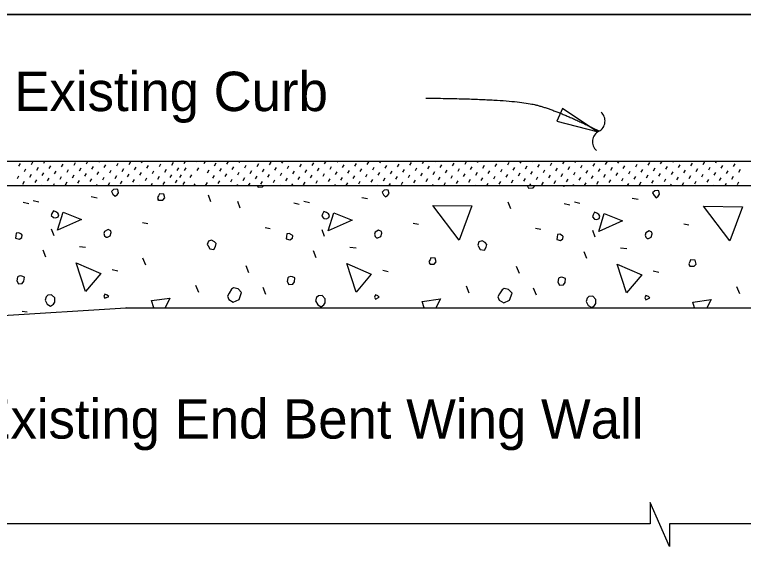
# Model space of a CAD drawing. Extents: x 0 to 41.1, y 0 to 25.9.
# Drawn here: x 12.993 to 16.72, y 6.378 to 9.099 of the extents above; entities that cross this region are included whole.
import ezdxf

# ---------------------------------------------------------------- set-up
doc = ezdxf.new("R2010")
doc.units = 0
for name, color, linetype in [('Dimension', 7, 'Continuous'), ('Miscellaneous', 7, 'Continuous'), ('TextStructures', 7, 'Continuous'), ('TrafBarrierConc', 7, 'Continuous')]:
    doc.layers.add(name, color=color, linetype=linetype)

msp = doc.modelspace()

# ---------------------------------------------------------------- linework, layer by layer
at = {"layer": 'Dimension'}
msp.add_lwpolyline([(15.9708, 8.5013), (15.7946, 8.6178), (15.7661, 8.5533)], close=True, dxfattribs=at)
for points in [[(14.7437, 6.4942), (12.1798, 6.4942), (12.1798, 6.3779), (12.0804, 6.6029), (12.0804, 6.4942), (10.5811, 6.4942)], [(18.3306, 6.4942), (16.3423, 6.4942), (16.3423, 6.3779), (16.243, 6.6029), (16.243, 6.4942), (14.7437, 6.4942)]]:
    msp.add_lwpolyline(points, dxfattribs=at)
for centre, start, end in [((15.9527, 8.5547), 297.3915, 49.1187), ((16.0076, 8.4488), 117.3915, 229.1187)]:
    msp.add_arc(centre, 0.0596, start, end, dxfattribs=at)
msp.add_open_spline([(15.0955, 8.6713), (15.5345, 8.6676), (15.7769, 8.6071), (15.9798, 8.5038)], degree=2, dxfattribs=at)
at = {"layer": 'Miscellaneous'}
for p, q in [((13.1424, 8.3394), (13.1479, 8.3489)), ((13.2059, 8.3475), (13.2067, 8.3489)), ((13.3606, 8.336), (13.3681, 8.3489)), ((13.4241, 8.3441), (13.4269, 8.3489)), ((13.6423, 8.3407), (13.647, 8.3489)), ((13.7057, 8.3488), (13.7058, 8.3489)), ((13.8604, 8.3373), (13.8671, 8.3489)), ((13.9239, 8.3454), (13.9259, 8.3489)), ((13.9623, 8.3373), (13.969, 8.3489)), ((14.0786, 8.3339), (14.0867, 8.3479)), ((14.1421, 8.342), (14.1461, 8.3489)), ((14.3603, 8.3386), (14.3662, 8.3489)), ((14.4238, 8.3467), (14.425, 8.3489)), ((14.5784, 8.3353), (14.5863, 8.3489)), ((14.6419, 8.3434), (14.6451, 8.3489)), ((14.8601, 8.34), (14.8653, 8.3489)), ((14.9236, 8.3481), (14.9241, 8.3489)), ((15.0783, 8.3366), (15.0854, 8.3489)), ((15.1418, 8.3447), (15.1442, 8.3489)), ((15.3599, 8.3413), (15.3643, 8.3489)), ((15.5781, 8.3379), (15.5845, 8.3489)), ((15.6416, 8.346), (15.6433, 8.3489)), ((15.7963, 8.3345), (15.8044, 8.3485)), ((15.8598, 8.3426), (15.8634, 8.3489)), ((16.0779, 8.3392), (16.0835, 8.3489)), ((16.1414, 8.3473), (16.1423, 8.3489)), ((16.2961, 8.3358), (16.3037, 8.3489)), ((16.3596, 8.344), (16.3625, 8.3489)), ((16.5778, 8.3406), (16.5826, 8.3489)), ((16.6413, 8.3487), (16.6414, 8.3489)), ((13.0154, 8.3232), (13.0235, 8.3372)), ((13.0789, 8.3313), (13.087, 8.3453)), ((13.1066, 8.3036), (13.1147, 8.3176)), ((13.1701, 8.3117), (13.1782, 8.3257)), ((13.2336, 8.3198), (13.2417, 8.3338)), ((13.2971, 8.3279), (13.3052, 8.3419)), ((13.3248, 8.3002), (13.3329, 8.3142)), ((13.3883, 8.3083), (13.3964, 8.3223)), ((13.4518, 8.3164), (13.4599, 8.3304)), ((13.5153, 8.3245), (13.5234, 8.3385)), ((13.543, 8.2968), (13.5511, 8.3108)), ((13.5788, 8.3326), (13.5869, 8.3466)), ((13.6065, 8.3049), (13.6146, 8.3189)), ((13.6699, 8.313), (13.678, 8.327)), ((13.7334, 8.3211), (13.7415, 8.3351)), ((13.7969, 8.3292), (13.805, 8.3432)), ((13.8246, 8.3015), (13.8327, 8.3155)), ((13.8623, 8.3015), (13.8704, 8.3155)), ((13.9265, 8.3015), (13.9346, 8.3155)), ((14.0151, 8.3258), (14.0232, 8.3398)), ((14.0428, 8.2981), (14.0509, 8.3121)), ((14.1063, 8.3062), (14.1144, 8.3202)), ((14.1698, 8.3143), (14.1779, 8.3283)), ((14.2333, 8.3224), (14.2414, 8.3364)), ((14.2968, 8.3305), (14.3049, 8.3445)), ((14.3245, 8.3028), (14.3326, 8.3168)), ((14.388, 8.311), (14.3961, 8.3249)), ((14.4514, 8.3191), (14.4596, 8.333)), ((14.5149, 8.3272), (14.523, 8.3412)), ((14.5426, 8.2995), (14.5507, 8.3135)), ((14.6061, 8.3076), (14.6142, 8.3216)), ((14.6696, 8.3157), (14.6777, 8.3297)), ((14.7331, 8.3238), (14.7412, 8.3378)), ((14.7966, 8.3319), (14.8047, 8.3459)), ((14.8243, 8.3042), (14.8324, 8.3182)), ((14.8878, 8.3123), (14.8959, 8.3263)), ((14.9513, 8.3204), (14.9594, 8.3344)), ((15.0148, 8.3285), (15.0229, 8.3425)), ((15.0425, 8.3008), (15.0506, 8.3148)), ((15.106, 8.3089), (15.1141, 8.3229)), ((15.1695, 8.317), (15.1776, 8.331)), ((15.2329, 8.3251), (15.2411, 8.3391)), ((15.2606, 8.2974), (15.2687, 8.3114)), ((15.2964, 8.3332), (15.3045, 8.3472)), ((15.3241, 8.3055), (15.3322, 8.3195)), ((15.3876, 8.3136), (15.3957, 8.3276)), ((15.4511, 8.3217), (15.4592, 8.3357)), ((15.5146, 8.3298), (15.5227, 8.3438)), ((15.5423, 8.3021), (15.5504, 8.3161)), ((15.6058, 8.3102), (15.6139, 8.3242)), ((15.6693, 8.3183), (15.6774, 8.3323)), ((15.7328, 8.3264), (15.7409, 8.3404)), ((15.7605, 8.2987), (15.7686, 8.3127)), ((15.824, 8.3068), (15.8321, 8.3208)), ((15.8875, 8.3149), (15.8956, 8.3289)), ((15.951, 8.323), (15.9591, 8.337)), ((16.0144, 8.3311), (16.0226, 8.3451)), ((16.0421, 8.3034), (16.0502, 8.3174)), ((16.1056, 8.3115), (16.1137, 8.3255)), ((16.1691, 8.3196), (16.1772, 8.3336)), ((16.2326, 8.3277), (16.2407, 8.3417)), ((16.2603, 8.3001), (16.2684, 8.314)), ((16.3238, 8.3082), (16.3319, 8.3221)), ((16.3873, 8.3163), (16.3954, 8.3303)), ((16.4508, 8.3244), (16.4589, 8.3384)), ((16.4785, 8.2967), (16.4866, 8.3107)), ((16.5143, 8.3325), (16.5224, 8.3465)), ((16.542, 8.3048), (16.5501, 8.3188)), ((16.6055, 8.3129), (16.6136, 8.3269)), ((16.669, 8.321), (16.6771, 8.335)), ((13.0073, 8.2597), (13.0154, 8.2737)), ((13.0431, 8.2955), (13.0512, 8.3095)), ((13.0708, 8.2678), (13.0789, 8.2818)), ((13.1343, 8.2759), (13.1424, 8.2899)), ((13.1978, 8.284), (13.2059, 8.298)), ((13.2613, 8.2921), (13.2694, 8.3061)), ((13.289, 8.2644), (13.2971, 8.2784)), ((13.3525, 8.2725), (13.3606, 8.2865)), ((13.416, 8.2806), (13.4241, 8.2946)), ((13.4795, 8.2887), (13.4876, 8.3027)), ((13.5072, 8.261), (13.5153, 8.275)), ((13.5707, 8.2691), (13.5788, 8.2831)), ((13.6342, 8.2772), (13.6423, 8.2912)), ((13.6976, 8.2853), (13.7057, 8.2993)), ((13.7611, 8.2934), (13.7692, 8.3074)), ((13.7888, 8.2657), (13.7969, 8.2797)), ((13.8388, 8.2657), (13.8469, 8.2797)), ((13.8907, 8.2657), (13.8988, 8.2797)), ((13.9793, 8.29), (13.9874, 8.304)), ((14.007, 8.2623), (14.0151, 8.2763)), ((14.0705, 8.2704), (14.0786, 8.2844)), ((14.134, 8.2785), (14.1421, 8.2925)), ((14.1975, 8.2866), (14.2056, 8.3006)), ((14.261, 8.2947), (14.2691, 8.3087)), ((14.2887, 8.2671), (14.2968, 8.281)), ((14.3522, 8.2752), (14.3603, 8.2891)), ((14.4157, 8.2833), (14.4238, 8.2973)), ((14.4791, 8.2914), (14.4872, 8.3054)), ((14.5068, 8.2637), (14.5149, 8.2777)), ((14.5703, 8.2718), (14.5784, 8.2858)), ((14.6338, 8.2799), (14.6419, 8.2939)), ((14.6973, 8.288), (14.7054, 8.302)), ((14.725, 8.2603), (14.7331, 8.2743)), ((14.7608, 8.2961), (14.7689, 8.3101)), ((14.7885, 8.2684), (14.7966, 8.2824)), ((14.852, 8.2765), (14.8601, 8.2905)), ((14.9155, 8.2846), (14.9236, 8.2986)), ((14.979, 8.2927), (14.9871, 8.3067)), ((15.0067, 8.265), (15.0148, 8.279)), ((15.0702, 8.2731), (15.0783, 8.2871)), ((15.1337, 8.2812), (15.1418, 8.2952)), ((15.1972, 8.2893), (15.2053, 8.3033)), ((15.2248, 8.2616), (15.2329, 8.2756)), ((15.2883, 8.2697), (15.2964, 8.2837)), ((15.3518, 8.2778), (15.3599, 8.2918)), ((15.4153, 8.2859), (15.4234, 8.2999)), ((15.4788, 8.294), (15.4869, 8.308)), ((15.5065, 8.2663), (15.5146, 8.2803)), ((15.57, 8.2744), (15.5781, 8.2884)), ((15.6335, 8.2825), (15.6416, 8.2965)), ((15.697, 8.2906), (15.7051, 8.3046)), ((15.7247, 8.2629), (15.7328, 8.2769)), ((15.7882, 8.271), (15.7963, 8.285)), ((15.8517, 8.2791), (15.8598, 8.2931)), ((15.9152, 8.2872), (15.9233, 8.3012)), ((15.9429, 8.2595), (15.951, 8.2735)), ((15.9787, 8.2953), (15.9868, 8.3093)), ((16.0063, 8.2676), (16.0144, 8.2816)), ((16.0698, 8.2757), (16.0779, 8.2897)), ((16.1333, 8.2838), (16.1414, 8.2978)), ((16.1968, 8.2919), (16.2049, 8.3059)), ((16.2245, 8.2643), (16.2326, 8.2782)), ((16.288, 8.2724), (16.2961, 8.2864)), ((16.3515, 8.2805), (16.3596, 8.2945)), ((16.415, 8.2886), (16.4231, 8.3026)), ((16.4427, 8.2609), (16.4508, 8.2749)), ((16.5062, 8.269), (16.5143, 8.283)), ((16.5697, 8.2771), (16.5778, 8.2911)), ((16.6332, 8.2852), (16.6413, 8.2992)), ((16.6967, 8.2933), (16.7048, 8.3073)), ((13.035, 8.232), (13.0431, 8.246)), ((13.0985, 8.2401), (13.1066, 8.2541)), ((13.162, 8.2482), (13.1701, 8.2622)), ((13.2255, 8.2563), (13.2336, 8.2703)), ((13.2532, 8.2286), (13.2613, 8.2426)), ((13.3167, 8.2367), (13.3248, 8.2507)), ((13.3802, 8.2448), (13.3883, 8.2588)), ((13.4437, 8.2529), (13.4518, 8.2669)), ((13.4714, 8.2252), (13.4795, 8.2392)), ((13.5349, 8.2333), (13.543, 8.2473)), ((13.5984, 8.2414), (13.6065, 8.2554)), ((13.6618, 8.2495), (13.6699, 8.2635)), ((13.7253, 8.2576), (13.7334, 8.2716)), ((13.753, 8.2299), (13.7611, 8.2439)), ((13.8165, 8.238), (13.8246, 8.252)), ((13.8549, 8.2299), (13.863, 8.2439)), ((13.9712, 8.2265), (13.9793, 8.2405)), ((14.0347, 8.2346), (14.0428, 8.2486)), ((14.0982, 8.2427), (14.1063, 8.2567)), ((14.1617, 8.2508), (14.1698, 8.2648)), ((14.1898, 8.2239), (14.1975, 8.2371)), ((14.2252, 8.259), (14.2333, 8.2729)), ((14.2529, 8.2313), (14.261, 8.2452)), ((14.3164, 8.2394), (14.3245, 8.2534)), ((14.3799, 8.2475), (14.388, 8.2615)), ((14.4433, 8.2556), (14.4514, 8.2696)), ((14.471, 8.2279), (14.4791, 8.2419)), ((14.5345, 8.236), (14.5426, 8.25)), ((14.598, 8.2441), (14.6061, 8.2581)), ((14.6615, 8.2522), (14.6696, 8.2662)), ((14.6892, 8.2245), (14.6973, 8.2385)), ((14.7527, 8.2326), (14.7608, 8.2466)), ((14.8162, 8.2407), (14.8243, 8.2547)), ((14.8797, 8.2488), (14.8878, 8.2628)), ((14.9432, 8.2569), (14.9513, 8.2709)), ((14.9709, 8.2292), (14.979, 8.2432)), ((15.0344, 8.2373), (15.0425, 8.2513)), ((15.0979, 8.2454), (15.106, 8.2594)), ((15.1614, 8.2535), (15.1695, 8.2675)), ((15.189, 8.2258), (15.1972, 8.2398)), ((15.2525, 8.2339), (15.2606, 8.2479)), ((15.316, 8.242), (15.3241, 8.256)), ((15.3795, 8.2501), (15.3876, 8.2641)), ((15.4081, 8.2239), (15.4153, 8.2364)), ((15.443, 8.2582), (15.4511, 8.2722)), ((15.4707, 8.2305), (15.4788, 8.2445)), ((15.5342, 8.2386), (15.5423, 8.2526)), ((15.5977, 8.2467), (15.6058, 8.2607)), ((15.6612, 8.2548), (15.6693, 8.2688)), ((15.6889, 8.2271), (15.697, 8.2411)), ((15.7524, 8.2352), (15.7605, 8.2492)), ((15.8159, 8.2433), (15.824, 8.2573)), ((15.8794, 8.2514), (15.8875, 8.2654)), ((15.9072, 8.2239), (15.9152, 8.2377)), ((15.9705, 8.2318), (15.9787, 8.2458)), ((16.034, 8.2399), (16.0421, 8.2539)), ((16.0975, 8.248), (16.1056, 8.262)), ((16.161, 8.2562), (16.1691, 8.2701)), ((16.1887, 8.2285), (16.1968, 8.2425)), ((16.2522, 8.2366), (16.2603, 8.2506)), ((16.3157, 8.2447), (16.3238, 8.2587)), ((16.3792, 8.2528), (16.3873, 8.2668)), ((16.4069, 8.2251), (16.415, 8.2391)), ((16.4704, 8.2332), (16.4785, 8.2472)), ((16.5339, 8.2413), (16.542, 8.2553)), ((16.5974, 8.2494), (16.6055, 8.2634)), ((16.6609, 8.2575), (16.669, 8.2715)), ((16.6886, 8.2298), (16.6967, 8.2438)), ((13.1329, 8.2239), (13.1343, 8.2264)), ((13.1917, 8.2239), (13.1978, 8.2345)), ((13.4118, 8.2239), (13.416, 8.2311)), ((13.6319, 8.2239), (13.6342, 8.2277)), ((13.6907, 8.2239), (13.6976, 8.2358)), ((13.8521, 8.2239), (13.8523, 8.2243)), ((13.9109, 8.2239), (13.9158, 8.2324)), ((14.131, 8.2239), (14.134, 8.229)), ((14.3511, 8.2239), (14.3522, 8.2257)), ((14.4099, 8.2239), (14.4157, 8.2338)), ((14.6301, 8.2239), (14.6338, 8.2304)), ((14.8502, 8.2239), (14.852, 8.227)), ((14.909, 8.2239), (14.9155, 8.2351)), ((15.1292, 8.2239), (15.1337, 8.2317)), ((15.3493, 8.2239), (15.3518, 8.2283)), ((15.5694, 8.2239), (15.57, 8.2249)), ((15.6282, 8.2239), (15.6335, 8.233)), ((15.8484, 8.2239), (15.8517, 8.2296)), ((16.0685, 8.2239), (16.0698, 8.2262)), ((16.1273, 8.2239), (16.1333, 8.2343)), ((16.3474, 8.2239), (16.3515, 8.231)), ((16.5676, 8.2239), (16.5697, 8.2276)), ((16.6264, 8.2239), (16.6332, 8.2357)), ((13.3845, 8.1673), (13.4146, 8.162)), ((13.9967, 8.1407), (13.9844, 8.1743)), ((14.7678, 8.1638), (14.7979, 8.1585)), ((13.0372, 8.1391), (13.0654, 8.132)), ((13.0889, 8.1483), (13.1172, 8.1413)), ((14.1464, 8.109), (14.1341, 8.1426)), ((14.4204, 8.1355), (14.4487, 8.1285)), ((14.4721, 8.1448), (14.5004, 8.1377)), ((15.5297, 8.1055), (15.5173, 8.1391)), ((15.8037, 8.132), (15.832, 8.1249)), ((15.8554, 8.1413), (15.8837, 8.1342)), ((16.1511, 8.1603), (16.1811, 8.155)), ((13.6479, 8.0348), (13.6744, 8.0295)), ((15.0312, 8.0312), (15.0577, 8.0259)), ((16.4145, 8.0277), (16.441, 8.0224)), ((13.1949, 7.9671), (13.1826, 8.0007)), ((14.2737, 8.01), (14.3002, 8.0047)), ((14.5782, 7.9636), (14.5658, 7.9972)), ((15.657, 8.0065), (15.6835, 8.0012)), ((15.9615, 7.9601), (15.9491, 7.9937)), ((13.3244, 7.9128), (13.3562, 7.9093)), ((14.7077, 7.9093), (14.7395, 7.9057)), ((16.091, 7.9057), (16.1228, 7.9022)), ((13.1525, 7.8575), (13.1384, 7.8929)), ((14.5358, 7.854), (14.5216, 7.8894)), ((15.9191, 7.8505), (15.9049, 7.8858)), ((13.6633, 7.8171), (13.6492, 7.8524)), ((13.4924, 7.7943), (13.5206, 7.7873)), ((14.1906, 7.7784), (14.1765, 7.8138)), ((14.8756, 7.7908), (14.9039, 7.7837)), ((15.5739, 7.7749), (15.5598, 7.8103)), ((16.2589, 7.7873), (16.2872, 7.7802)), ((13.9343, 7.6777), (13.9202, 7.713)), ((14.2777, 7.6666), (14.2636, 7.702)), ((15.3176, 7.6741), (15.3034, 7.7095)), ((15.661, 7.6631), (15.6468, 7.6984)), ((16.7009, 7.6706), (16.6867, 7.706)), ((13.0323, 7.5818), (13.0571, 7.5782))]:
    msp.add_line(p, q, dxfattribs=at)
for points in [[(13.4959, 8.1797), (13.5065, 8.1691), (13.5171, 8.1762), (13.5242, 8.1868), (13.5206, 8.2045), (13.5118, 8.2062), (13.4994, 8.2045), (13.4888, 8.1939), (13.4959, 8.1797)], [(14.2329, 8.2238), (14.2384, 8.2151), (14.2613, 8.2168), (14.2683, 8.2238)], [(14.8792, 8.1762), (14.8898, 8.1656), (14.9004, 8.1727), (14.9075, 8.1833), (14.9039, 8.2009), (14.8951, 8.2027), (14.8827, 8.2009), (14.8721, 8.1903), (14.8792, 8.1762)], [(15.614, 8.2238), (15.6216, 8.2115), (15.6446, 8.2133), (15.6535, 8.2221), (15.6552, 8.2238)], [(15.8006, 8.2173), (15.7985, 8.2238)], [(15.804, 8.2238), (15.8006, 8.2173)], [(16.2625, 8.1727), (16.2731, 8.162), (16.2837, 8.1691), (16.2907, 8.1797), (16.2872, 8.1974), (16.2784, 8.1992), (16.266, 8.1974), (16.2554, 8.1868), (16.2625, 8.1727)], [(13.7297, 8.1501), (13.7509, 8.1501), (13.7615, 8.1608), (13.7562, 8.1802), (13.7332, 8.182), (13.7297, 8.1714), (13.7244, 8.1625), (13.7297, 8.1501), (13.7262, 8.1537)], [(13.1914, 8.06), (13.2038, 8.0582), (13.2161, 8.0635), (13.2197, 8.0741), (13.2144, 8.0829), (13.2038, 8.09), (13.1914, 8.0953), (13.1843, 8.0812), (13.1808, 8.0706), (13.1914, 8.06)], [(13.2131, 7.9959), (13.2413, 8.0878), (13.335, 8.0507), (13.2131, 7.9959)], [(14.5747, 8.0564), (14.5871, 8.0547), (14.5994, 8.06), (14.603, 8.0706), (14.5977, 8.0794), (14.5871, 8.0865), (14.5747, 8.0918), (14.5676, 8.0776), (14.5641, 8.067), (14.5747, 8.0564)], [(15.2663, 7.9446), (15.132, 8.1214), (15.3317, 8.1196), (15.2663, 7.9446)], [(15.958, 8.0529), (15.9703, 8.0511), (15.9827, 8.0564), (15.9862, 8.067), (15.9809, 8.0759), (15.9703, 8.0829), (15.958, 8.0882), (15.9509, 8.0741), (15.9473, 8.0635), (15.958, 8.0529)], [(16.6496, 7.9411), (16.5152, 8.1179), (16.715, 8.1161), (16.6496, 7.9411)], [(14.5963, 7.9923), (14.6246, 8.0843), (14.7183, 8.0471), (14.5963, 7.9923)], [(15.9796, 7.9888), (16.0079, 8.0807), (16.1016, 8.0436), (15.9796, 7.9888)], [(12.9983, 7.9552), (13.0177, 7.9499), (13.0301, 7.9588), (13.0319, 7.9711), (13.0283, 7.9747), (13.0142, 7.9817), (13.0018, 7.98), (13, 7.9676), (12.9983, 7.9552)], [(13.4605, 7.9605), (13.4676, 7.9605), (13.4818, 7.9676), (13.4871, 7.9835), (13.4853, 7.9923), (13.4712, 7.9994), (13.4535, 7.9888), (13.4499, 7.9782), (13.4535, 7.9676), (13.4605, 7.9605)], [(14.3816, 7.9517), (14.401, 7.9464), (14.4134, 7.9552), (14.4151, 7.9676), (14.4116, 7.9711), (14.3975, 7.9782), (14.3851, 7.9764), (14.3833, 7.9641), (14.3816, 7.9517)], [(14.8438, 7.957), (14.8509, 7.957), (14.865, 7.9641), (14.8703, 7.98), (14.8686, 7.9888), (14.8544, 7.9959), (14.8368, 7.9853), (14.8332, 7.9747), (14.8368, 7.9641), (14.8438, 7.957)], [(16.2271, 7.9534), (16.2342, 7.9534), (16.2483, 7.9605), (16.2536, 7.9764), (16.2518, 7.9853), (16.2377, 7.9923), (16.22, 7.9817), (16.2165, 7.9711), (16.22, 7.9605), (16.2271, 7.9534)], [(13.982, 7.9163), (13.9909, 7.9004), (14.0121, 7.8969), (14.0209, 7.9128), (14.0245, 7.9269), (14.0156, 7.9358), (13.9997, 7.9446), (13.9838, 7.9393), (13.9785, 7.9234), (13.982, 7.9163)], [(15.3653, 7.9128), (15.3742, 7.8969), (15.3954, 7.8933), (15.4042, 7.9093), (15.4077, 7.9234), (15.3989, 7.9322), (15.383, 7.9411), (15.3671, 7.9358), (15.3618, 7.9199), (15.3653, 7.9128)], [(15.7648, 7.9481), (15.7843, 7.9428), (15.7966, 7.9517), (15.7984, 7.9641), (15.7949, 7.9676), (15.7807, 7.9747), (15.7684, 7.9729), (15.7666, 7.9605), (15.7648, 7.9481)], [(13.3558, 7.6825), (13.3081, 7.8293), (13.4336, 7.7745), (13.3558, 7.6825)], [(15.1173, 7.8226), (15.1385, 7.8226), (15.1491, 7.8332), (15.1438, 7.8527), (15.1208, 7.8545), (15.1173, 7.8438), (15.1119, 7.835), (15.1173, 7.8226), (15.1137, 7.8262)], [(16.4463, 7.812), (16.4675, 7.812), (16.4781, 7.8226), (16.4728, 7.8421), (16.4498, 7.8438), (16.4463, 7.8332), (16.441, 7.8244), (16.4463, 7.812), (16.4428, 7.8156)], [(14.7391, 7.679), (14.6914, 7.8257), (14.8169, 7.7709), (14.7391, 7.679)], [(16.1224, 7.6755), (16.0746, 7.8222), (16.2001, 7.7674), (16.1224, 7.6755)], [(13.004, 7.7373), (13.0129, 7.7214), (13.0323, 7.7232), (13.0411, 7.7356), (13.0429, 7.755), (13.0305, 7.7603), (13.0217, 7.7621), (13.0111, 7.7586), (13.0076, 7.755), (13.004, 7.7373)], [(14.3873, 7.7338), (14.3961, 7.7179), (14.4156, 7.7197), (14.4244, 7.732), (14.4262, 7.7515), (14.4138, 7.7568), (14.405, 7.7586), (14.3944, 7.755), (14.3908, 7.7515), (14.3873, 7.7338)], [(15.7706, 7.7303), (15.7794, 7.7144), (15.7989, 7.7161), (15.8077, 7.7285), (15.8095, 7.7479), (15.7971, 7.7532), (15.7883, 7.755), (15.7776, 7.7515), (15.7741, 7.7479), (15.7706, 7.7303)], [(14.0881, 7.6406), (14.1111, 7.6282), (14.1411, 7.6406), (14.1535, 7.6777), (14.1358, 7.6954), (14.1128, 7.7007), (14.1022, 7.6936), (14.0899, 7.6741), (14.081, 7.6582), (14.0881, 7.6406)], [(15.4714, 7.637), (15.4944, 7.6246), (15.5244, 7.637), (15.5368, 7.6741), (15.5191, 7.6918), (15.4961, 7.6971), (15.4855, 7.6901), (15.4731, 7.6706), (15.4643, 7.6547), (15.4714, 7.637)], [(13.149, 7.6383), (13.1596, 7.6171), (13.1773, 7.6065), (13.1914, 7.6171), (13.1985, 7.6277), (13.1985, 7.649), (13.1826, 7.6649), (13.1631, 7.6631), (13.1543, 7.6543), (13.149, 7.6383)], [(13.4548, 7.6472), (13.4742, 7.656), (13.4672, 7.6631), (13.4548, 7.6684), (13.4495, 7.656), (13.4548, 7.6472)], [(13.7056, 7.5989), (13.6939, 7.6353), (13.7876, 7.6476), (13.7625, 7.5989)], [(14.5323, 7.6348), (14.5429, 7.6136), (14.5605, 7.603), (14.5747, 7.6136), (14.5817, 7.6242), (14.5817, 7.6454), (14.5658, 7.6613), (14.5464, 7.6596), (14.5376, 7.6507), (14.5323, 7.6348)], [(14.8381, 7.6436), (14.8575, 7.6525), (14.8505, 7.6596), (14.8381, 7.6649), (14.8328, 7.6525), (14.8381, 7.6436)], [(15.0877, 7.5989), (15.0772, 7.6317), (15.1709, 7.6441), (15.1476, 7.5989)], [(15.9155, 7.6313), (15.9261, 7.6101), (15.9438, 7.5995), (15.958, 7.6101), (15.965, 7.6207), (15.965, 7.6419), (15.9491, 7.6578), (15.9297, 7.656), (15.9208, 7.6472), (15.9155, 7.6313)], [(16.2214, 7.6401), (16.2408, 7.649), (16.2337, 7.656), (16.2214, 7.6613), (16.2161, 7.649), (16.2214, 7.6401)], [(16.4699, 7.5989), (16.4604, 7.6282), (16.5541, 7.6406), (16.5327, 7.5989)], [(13.5636, 7.5989), (13.5626, 7.5995), (13.5612, 7.5989)]]:
    msp.add_lwpolyline(points, dxfattribs=at)
at = {"layer": 'TrafBarrierConc'}
for p, q in [((18.3647, 9.0989), (8.3411, 9.0989)), ((12.1382, 9.0989), (18.4751, 9.0989)), ((8.3411, 8.3489), (20.0548, 8.3489)), ((10.3412, 8.2239), (20.0548, 8.2239)), ((9.5611, 7.3489), (13.5611, 7.5989)), ((13.561, 7.5988), (20.0547, 7.5988))]:
    msp.add_line(p, q, dxfattribs=at)

# ---------------------------------------------------------------- texts
at = {"layer": 'TextStructures'}
for s, p in [('Existing Curb', (12.992, 8.6051)), ('Existing End Bent Wing Wall', (12.7924, 6.9296))]:
    msp.add_text(s, height=0.2016, dxfattribs=at).set_placement(p)

doc.saveas('drawing.dxf')
